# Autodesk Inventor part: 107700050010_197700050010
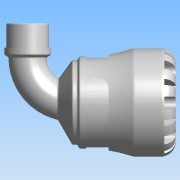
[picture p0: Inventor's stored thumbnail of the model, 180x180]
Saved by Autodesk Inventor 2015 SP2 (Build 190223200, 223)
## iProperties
Created: 2016-12
Part Number: 107700050010_197700050010
Material: PVC-Piping
Description: PLASSON 90° ELBOW WITH MALE INTEGRAL BRASS 50X1" SERIES 1
Document SubType Name: Modeling
Designer: KIM
Mass: 664.223 g
Surface Area: 733.008 cm^2
Volume: 474.445 cm^3
Density: 1.4 g/cm^3
Appearance: Smooth - White
Author: KIM
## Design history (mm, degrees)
derived "1077.ipt"
feature "Solid1::1077.ipt"
tag "TaggingFeature1"
body "Solid1"
other parameters: "d1" = 33.18, "d3" = 62.5, "d4" = 85, "d8" = 72.25, "d13" = 9, "d14" = 9, "d15" = 0, "d17" = 360 deg, "d19" = 8 deg, "d20" = 1, "d21" = 1, "d22" = 8 deg, "d24" = 0, "d26" = 360 deg, "d33" = 8.5, "d43" = 66.3, "d51" = 0.85, "d54" = 17.5, "d55" = 11, "d57" = 17.64, "d58" = 0, "d74" = 0, "d78" = 79, "d82" = 1, "d115" = 360 deg, "d207" = 90 deg, "d228" = 14.875, "d247" = 1.7, "d248" = 4.74, "d268" = 39.7375, "d269" = 4.74, "d270" = 116, "d276" = 33.249, "d277" = 19, "d278" = 36.5739, "d279" = 62, "d280" = 24.7, "d281" = 4.98735, "d283" = 29.9241, "d286" = 0, "d287" = 0, "d288" = 23.2743, "d290" = 18.18795, "d292" = 30 deg, "d294" = 3.3249, "d296" = 30 deg, "E_" = 85, "l_" = 79, "A_" = 116, "A_1" = 62, "l_2" = 19, "R_" = 33.249, "d9" = 11.25, "d11" = 85, "d12" = 62.5, "d289" = 23.2743
